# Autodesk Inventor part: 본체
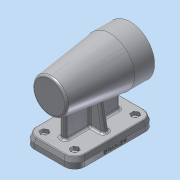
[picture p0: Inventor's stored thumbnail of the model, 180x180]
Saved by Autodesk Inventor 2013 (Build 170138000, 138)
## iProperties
Created: 2017-01
Part Number: 본체
Material: 알루미늄 6061
Document SubType Name: Modeling
Designer: dgall
Density: 1 g/cm^3
Author: dgall
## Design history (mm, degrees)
sketch "스케치1"
  geometry: C1 r 34 at (0, 0); 1 further point
  constraints: 1 centre point, 1 coincident
  dimensions: "d0" = 68 diameter of C1
extrude "돌출1" new body sketch "스케치1" distance "d2" = 28; taper "d3" = 0 deg
sketch "스케치2"
  geometry: C1 r 34 at (0, 0) reference; C2 r 34 at (0, 0)
  constraints: 1 centre point, 1 coincident, 1 concentric
extrude "돌출2" join sketch "스케치2" distance "d4" = 84; taper "d5" = -7 deg
node "작업 평면1"
sketch "스케치3"
  geometry: L1 (-35, -84)-(35, -84); L2 (35, -84)-(35, 28); L3 (35, 28)-(-35, 28); L4 (-35, 28)-(-35, -84); L5 (-34, 0)-(-23.686, -84) reference; L6 (-34, 0)-(-34, 28) reference; L7 (-30.562, -28)-(-14.801, -28); L8 (23.686, -84)-(-23.686, -84) reference; L9 (0, -84)-(0, -66.42); 1 further point
  constraints: 12 end point, 3 perpendicular, 2 parallel, 1 horizontal, 1 midpoint, 1 point on line
  dimensions: "d7" = 56 vertical distance of L7.start L5.end; "d8" = 56 distance between parallel lines of L1 L7; "d9" = 56 distance between parallel lines of L3 L7; "d10" = 35 distance between parallel lines of L4 L9; "d11" = 35 distance between parallel lines of L9 L2
extrude "돌출3" join sketch "스케치3" distance "d12" = 7; taper "d13" = 0 deg
sketch "스케치4"
  geometry: L1 (-35, -84)-(35, -84) reference; L2 (35, -84)-(35, 28) reference; L3 (35, 28)-(-35, 28) reference; L4 (-35, -84)-(35, -84); L5 (35, -84)-(35, 28); L6 (35, 28)-(-35, 28); L7 (-35, 28)-(-35, -84); 1 further point
  constraints: 8 end point, 2 parallel, 1 horizontal, 1 perpendicular, 1 point on line
  dimensions: "d14" = 0 distance between parallel lines of L3 L6
extrude "돌출4" join sketch "스케치4" distance "d15" = 7; taper "d16" = -15 deg
node "작업 평면2"
sketch "스케치5"
  geometry: L1 (-82.124, -60)-(26.124, -60) reference; L2 (0, -34)-(-84, -23.686) reference; L3 (0, -34)-(28, -34) reference; L4 (-66, -25.896)-(-66, -60); L5 (-84, -74)-(-84, -67) reference; L6 (10, -34)-(10, -60); L7 (28, -74)-(28, -67) reference; L8 (-66, -60)-(10, -60); L9 (-66, -25.896)-(0, -34); L10 (10, -34)-(0, -34); 1 further point
  constraints: 10 end point, 4 point on line, 3 collinear, 2 perpendicular
  dimensions: "d18" = 18 distance from line of L4.end L5; "d19" = 18 distance from line of L6.end L7
extrude "돌출5" join sketch "스케치5" stored distance "d20" = 8; taper "d21" = 0 deg
node "작업 평면3"
sketch "스케치6"
  geometry: L1 (-33.124, -60)-(33.124, -60) reference; L2 (-23, -60)-(-17.555, -29.118); L3 (-35, -74)-(-35, -67) reference; 2 further points
  constraints: 2 end point, 1 point on line
  dimensions: "d23" = 12 distance from line of L2.start L3; "d24" = 100 deg angle of L1 L2
sketch "스케치7"
  geometry: C1 r 34 at (0, 0) reference; C2 r 21 at (0, 0)
  constraints: 1 centre point, 1 coincident
  dimensions: "d25" = 42 diameter of C2
extrude "돌출6" cut sketch "스케치7" distance "d27" = 15; taper "d28" = 0 deg
sketch "스케치8"
  geometry: C1 r 21 at (0, 0) reference; C2 r 24 at (0, 0)
  constraints: 1 centre point, 1 coincident
  dimensions: "d29" = 48 diameter of C2
extrude "돌출7" cut sketch "스케치8" distance "d31" = 54; taper "d32" = 0 deg
sketch "스케치9"
  geometry: C1 r 21 at (0, 0) reference
extrude "돌출8" cut sketch "스케치9" distance "d33" = 54; taper "d34" = 0 deg
sketch "스케치10"
  geometry: C1 r 24 at (0, 0) reference; C2 r 21 at (0, 0)
  constraints: 1 centre point, 1 coincident
  dimensions: "d35" = 42 diameter of C2
extrude "돌출9" cut sketch "스케치10" distance "d37" = 12; taper "d38" = 0 deg
sketch "스케치11"
  geometry: C1 r 21 at (0, 0) reference; C2 r 17.5 at (0, 0)
  constraints: 1 centre point, 1 coincident
  dimensions: "d39" = 35 diameter of C2
extrude "돌출10" cut sketch "스케치11" distance "d41" = 18; taper "d42" = 0 deg
sketch "스케치12"
  geometry: C1 r 17.5 at (0, 0) reference; C2 r 16 at (0, 0)
  constraints: 1 centre point, 1 coincident
  dimensions: "d43" = 32 diameter of C2
extrude "돌출11" cut sketch "스케치12" distance "d45" = 4; taper "d46" = 0 deg
sketch "스케치13"
  geometry: C1 r 16 at (0, 0) reference; C2 r 10.5 at (0, 0)
  constraints: 1 centre point, 1 coincident
  dimensions: "d47" = 21 diameter of C2
extrude "돌출12" cut sketch "스케치13" distance "d49" = 3; taper "d50" = 0 deg
sketch "스케치14"
  geometry: C1 r 21 at (0, 0) reference; C2 r 34 at (0, 0) reference; C3 r 2 at (0, -26); C4 r 2 at (26, 0); C5 r 2 at (0, 26); C6 r 2 at (-26, 0); A1 r 26 centre (0, 0) between (0, -26) and (26, 0)
  constraints: 5 centre point, 4 point on circle, 2 horizontal alignment, 2 vertical alignment, 1 coincident
  dimensions: "d51" = 52 diameter of A1; "d53" = 4 diameter of C3; "d54" = 4 diameter of C4; "d55" = 4 diameter of C5; "d56" = 4 diameter of C6
hole "구멍1" sketch "스케치14" at (0, -26), (26, 0), (0, 26), (-26, 0) diameter "d57" = 3.242; stored, may be unused: countersink angle "d61" = 82 deg, drill point angle "d63" = 118 deg; dims "d58" = 8, "d59" = 3.023, "d60" = 2, "d62" = 11
node "작업 평면4"
sketch "스케치15"
  geometry: L1 (-33.124, -60)-(33.124, -60) reference; L2 (-23, -60)-(-15.632, -18.211); L3 (-35, -74)-(-35, -67) reference; L4 (35, -74)-(35, -67) reference; C1 r 21 at (0, 0) reference; C2 r 21 at (0, 0) reference; 2 further points
  constraints: 2 end point, 1 point on line, 2 other
  dimensions: "d65" = 12 distance from line of L2.start L3; "d67" = 100 deg angle of L1 L2
feature "리브1" sketch "스케치15" dims "d68" = 1, "d69" = 8, "d70" = 0, "d71" = 0, "d72" = 1, "d73" = 1
sketch "스케치16"
  geometry: L1 (-33.124, -60)-(33.124, -60) reference; L2 (15.632, -18.211)-(23, -60); L3 (35, -74)-(35, -67) reference; 2 further points
  constraints: 2 end point, 1 point on line, 2 other
  dimensions: "d74" = 12 distance from line of L2.end L3; "d75" = 100 deg angle of L1 L2
feature "리브2" sketch "스케치16" dims "d76" = 1, "d77" = 8, "d78" = 0, "d79" = 0, "d80" = 1, "d81" = 1
chamfer "모따기1" distance "d82" = 1; stored, may be unused: second distance "d83" = 2, angle "d84" = 45 deg
fillet "모깎기1" dims "d85" = 3
fillet "모깎기2" dims "d86" = 3
fillet "모깎기3" dims "d87" = 3
sketch "스케치19"
  geometry: L1 (-33.124, -82.124)-(-33.124, 26.124) reference; L2 (33.124, -82.124)-(-33.124, -82.124) reference; L3 (7, -21)-(7, 7) reference; L4 (-33.124, -28)-(-27.927, -28); L5 (0, -82.124)-(0, -76.165); L6 (-16, -67.113)-(-16, -72.887); L7 (-16, -72.887)-(-21, -75.774); L8 (-21, -75.774)-(-26, -72.887); L9 (-26, -72.887)-(-26, -67.113); L10 (-26, -67.113)-(-21, -64.226); L11 (-21, -64.226)-(-16, -67.113); L12 (26, -67.113)-(26, -72.887); L13 (26, -72.887)-(21, -75.774); L14 (21, -75.774)-(16, -72.887); L15 (16, -72.887)-(16, -67.113); L16 (16, -67.113)-(21, -64.226); L17 (21, -64.226)-(26, -67.113); L18 (-16, 16.887)-(-16, 11.113); L19 (-16, 11.113)-(-21, 8.226); L20 (-21, 8.226)-(-26, 11.113); L21 (-26, 11.113)-(-26, 16.887); L22 (-26, 16.887)-(-21, 19.774); L23 (-21, 19.774)-(-16, 16.887); L24 (26, 16.887)-(26, 11.113); L25 (26, 11.113)-(21, 8.226); L26 (21, 8.226)-(16, 11.113); L27 (16, 11.113)-(16, 16.887); L28 (16, 16.887)-(21, 19.774); L29 (21, 19.774)-(26, 16.887); C1 r 5 at (-21, -70); C2 r 5 at (21, -70); C3 r 5 at (-21, 14); C4 r 5 at (21, 14); 5 further points
  constraints: 52 end point, 11 tangent, 4 centre point, 2 midpoint, 2 perpendicular, 52 other
  dimensions: "d102" = 42 distance from line of C1.centre L4; "d104" = 42 distance from line of C3.centre L4; "d105" = 42 distance from line of C2.centre L4; "d106" = 42 distance from line of C4.centre L4; "d107" = 21 distance from line of C1.centre L5; "d108" = 21 distance from line of L5 C2.centre; "d109" = 21 horizontal distance of C3.centre L5.end; "d110" = 21 distance from line of C4.centre L5; "d111" = 10 diameter of C1; "d112" = 10 diameter of C3; "d113" = 10 diameter of C2; "d114" = 10 diameter of C4; "d115" = 0 distance of C1.centre point (-21, -70); "d116" = 0 horizontal distance of L8.end L9.end; "d117" = 0 horizontal distance of L14.end L15.end; "d118" = 0 horizontal distance of L21.end L20.end; "d119" = 0 horizontal distance of L26.end L27.end
extrude "돌출14" cut sketch "스케치19" distance "d120" = 5; taper "d121" = 0 deg
fillet "모깎기4" dims "d122" = 3
fillet "모깎기5" dims "d123" = 0.3
fillet "모깎기6" dims "d124" = 2
sketch "스케치20"
  geometry: L1 (-26, -72.887)-(-26, -67.113) reference; L2 (-26, -70)-(-21, -70); C1 r 2.5 at (-21, -70); 2 further points
  constraints: 2 end point, 1 centre point, 1 coincident, 1 midpoint, 1 perpendicular, 1 vertical alignment
  dimensions: "d125" = 5 diameter of C1
extrude "돌출15" cut sketch "스케치20" stored distance "d127" = 5; taper "d128" = 0 deg
sketch "스케치21"
  geometry: L1 (16, -72.887)-(16, -67.113) reference; L2 (16, -70)-(18.133, -70); C1 r 2.5 at (21, -70); 2 further points
  constraints: 2 end point, 1 centre point, 1 midpoint, 1 perpendicular, 1 vertical alignment
  dimensions: "d129" = 0 distance from line of C1.centre L2; "d131" = 5 diameter of C1
extrude "돌출16" cut sketch "스케치21" stored distance "d132" = 5; taper "d133" = 0 deg
sketch "스케치22"
  geometry: L1 (-26, 11.113)-(-26, 16.887) reference; L2 (-26, 14)-(-24.496, 14); C1 r 2.5 at (-21, 14); 2 further points
  constraints: 2 end point, 1 centre point, 1 midpoint, 1 perpendicular, 1 vertical alignment
  dimensions: "d134" = 0 distance from line of C1.centre L2; "d136" = 5 diameter of C1
extrude "돌출17" cut sketch "스케치22" stored distance "d137" = 5; taper "d138" = 0 deg
sketch "스케치23"
  geometry: L1 (16, 11.113)-(16, 16.887) reference; L2 (16, 14)-(26, 14); C1 r 2.5 at (21, 14); 3 further points
  constraints: 2 end point, 2 midpoint, 1 centre point, 1 coincident, 1 perpendicular, 1 vertical alignment
  dimensions: "d139" = 5 diameter of C1
extrude "돌출18" cut sketch "스케치23" stored distance "d141" = 5; taper "d142" = 0 deg
fillet "모깎기7" dims "d143" = 14
fillet "모깎기8" dims "d144" = 1
node "작업 평면5"
sketch "스케치24"
  geometry: L1 (-53.253, -67.598)-(-2.747, -67.598); L2 (-2.747, -67.598)-(-2.747, -72.402); L3 (-2.747, -72.402)-(-53.253, -72.402); L4 (-53.253, -72.402)-(-53.253, -67.598); L5 (-53.253, -70)-(-2.747, -70); L6 (-28, -67.598)-(-28, -72.402); L7 (-70, -74)-(14, -74) reference; L8 (28, -74)-(28, -67) reference; 1 further point
  constraints: 4 end point, 4 midpoint, 2 other
  dimensions: "d146" = 4 distance from line of L5.start L7; "d147" = 56 distance between parallel lines of L6 L8
feature "엠보싱1" sketch "스케치24" dims "d9" = 56, "d148" = 0.5, "d149" = 0
fillet "모깎기9" dims "d150" = 3
node "솔리드1"
node "투영된 루프1"
other parameters: "d6" = -74, "d17" = 0, "d22" = -56, "d64" = -56, "d145" = 64.75
